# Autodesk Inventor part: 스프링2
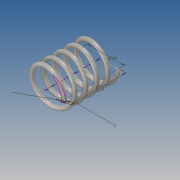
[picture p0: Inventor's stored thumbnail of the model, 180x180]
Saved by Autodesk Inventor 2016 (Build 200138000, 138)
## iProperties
Created: 2016-10
Part Number: 스프링2
Material: 강철, 탄소
Document SubType Name: Modeling
Designer: Administrator
Density: 7.85 g/cm^3
Appearance: 반연마
Mass: 6.86321 g
Surface Area: 17.7466 cm^2
Volume: 0.874294 cm^3
Author: Administrator
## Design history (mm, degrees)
sketch "스케치1"
  geometry: L1 (0, 0)-(-9, 0); L2 (-9, 0)-(-9, -27); L3 (-9, -27)-(0, -27); L4 (0, -27)-(0, 0); C1 r 1 at (-9, 0)
  constraints: 8 end point, 2 parallel, 1 centre point, 1 coincident, 1 horizontal, 1 perpendicular
  dimensions: "d0" = 2 diameter of C1; "d1" = 27 distance of L1.end L2.end (derived); "d2" = 18 diameter of L2 L4
feature "코일1" pitch "d3" = 10; turns "d5" = 5; dims "d4" = 27 (= d1), "d6" = 0, angle "d7" = 90 deg, angle "d8" = 90 deg, "d9" = 0, "d10" = 0
sketch "스케치2"
  geometry: L1 (10, 0)-(8, 0) reference; 1 further point
  constraints: 1 horizontal alignment
  node "절단 모서리 투영1"
extrude "돌출1" cut sketch "스케치2" stored distance "d11" = 10; taper "d12" = 0 deg
node "작업 평면3"
sketch "스케치3"
  geometry: L1 (-1, 0)-(1, 0) reference; 1 further point
  constraints: 1 horizontal alignment
extrude "돌출2" cut sketch "스케치3" stored distance "d14" = 0; taper "d15" = 0 deg
node "솔리드1"
node "절단 모서리 투영2"
other parameters: "d13" = 90 deg
